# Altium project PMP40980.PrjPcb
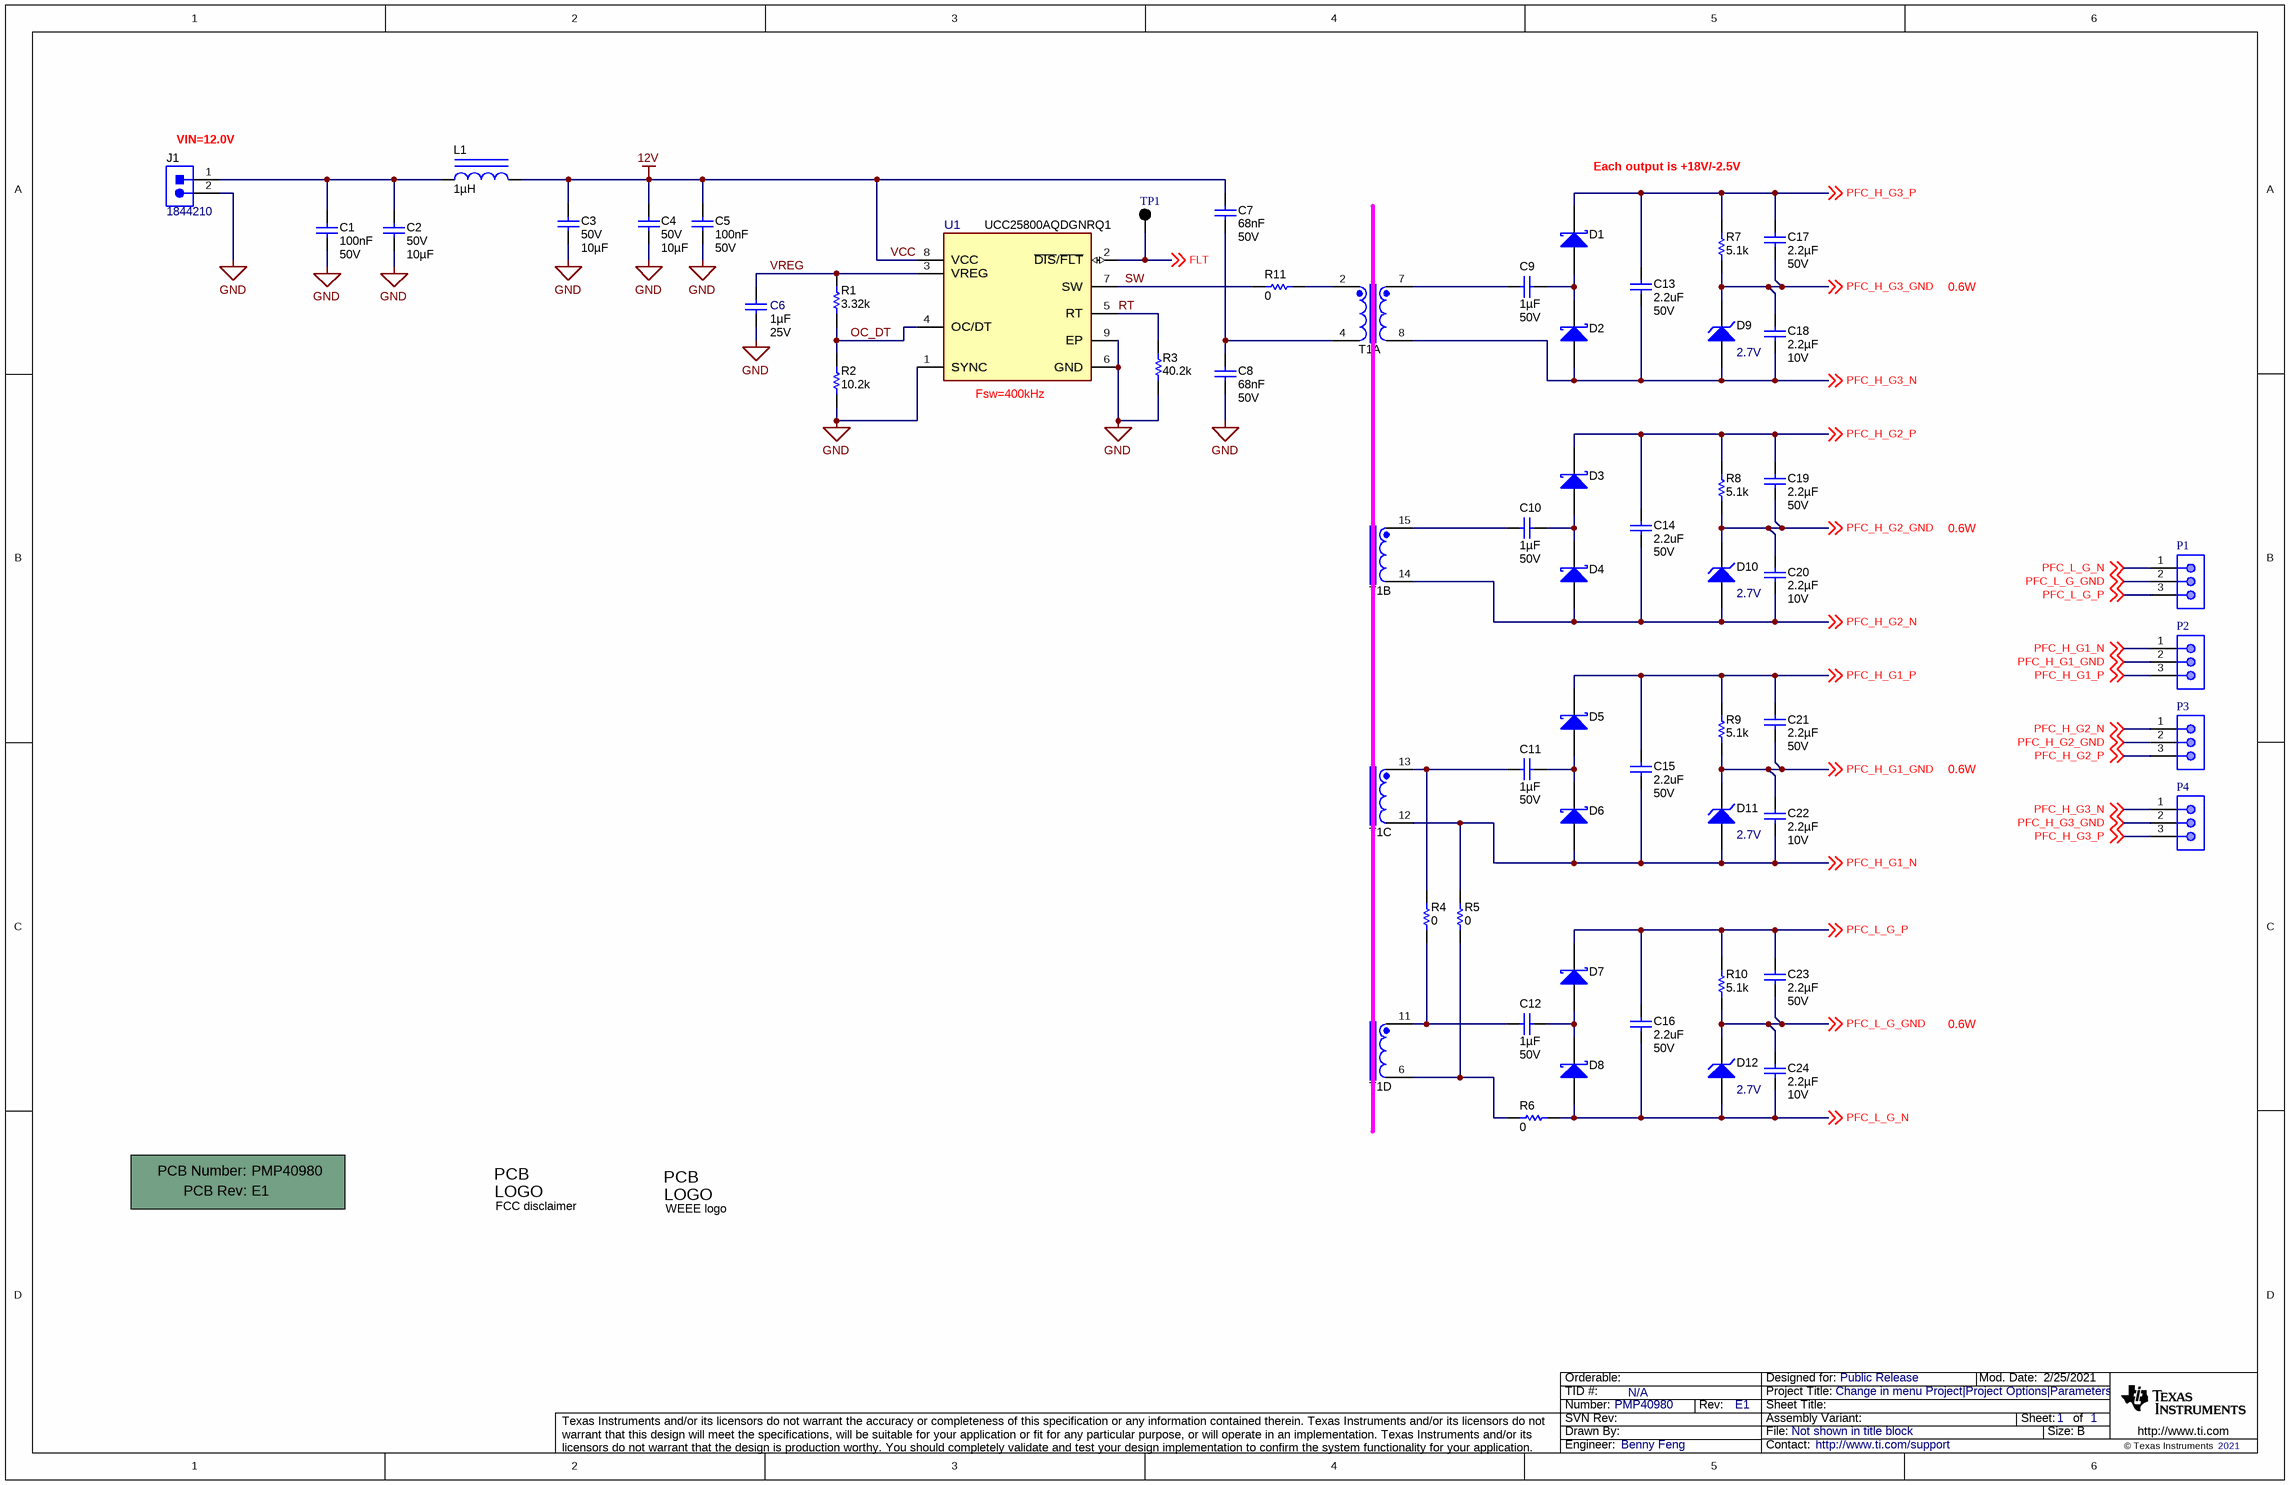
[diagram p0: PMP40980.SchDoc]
CopyrightYear: 2021; PCB_Layout: Benny Feng; PCB_Rev: E1; PRJ_Customer: Public Release; PRJ_Engineer: Benny Feng; PRJ_Number: PMP40980; PRJ_Title: Change in menu Project|Project Options|Parameters; SCH_Rev: E1; TechSupport: http://www.ti.com/support; TID: N/A
1 sheet, 59 parts. Net scope: global (net labels, ports and power ports of the same name join across sheets).
Board file: PMP40980.PcbDoc

## Sheet PMP40980.SchDoc
size 431 x 279 mm; Date: Not shown in title block; ApprovedBy: Not shown in title block; CheckedBy: Not shown in title block; Author: Not shown in title block; CompanyName: Not shown in title block; Engineer: Not shown in title block; Organization: Not shown in title block; Address1: Not shown in title block; Address2: Not shown in title block; Address3: Not shown in title block; Address4: Not shown in title block; DocumentNumber: 1; Revision: Use project parameter SCH_Rev; SheetNumber: 1; SheetTotal: 1; PageSetup: Record=PageOptions¦CenterHorizontal=True¦CenterVertical=True¦PrintScale=1.00¦XCorrection=1.00¦YCorrection=1.00¦PrintKind=0¦BorderSize=5000000¦LeftOffset=0¦BottomOffset=0¦Orientation=2¦PaperLength=1000¦PaperWidth=1000¦Scale=100¦PaperSource=15¦PrintQuality=600¦MediaType=1¦DitherType=10¦PaperKind=Letter¦PrintScaleMode=1

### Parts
!PCB1  Printed Circuit Board  (value not drawn)  (mechanical)
C1  Cap_F: 100nF  VDC_V: 50V  [0603L]  (hidden comment: CGA3E2X7R1H104K080AA)
C2  VDC_V: 50V  ValueDisplayed: 10µF  [1206_190L]  (hidden comment: CGA5L1X7R1H106K160AC)
C3  VDC_V: 50V  ValueDisplayed: 10µF  [1206_190L]  (hidden comment: CGA5L1X7R1H106K160AC)
C4  VDC_V: 50V  ValueDisplayed: 10µF  [1206_190L]  (hidden comment: CGA5L1X7R1H106K160AC)
C5  Cap_F: 100nF  VDC_V: 50V  [0603L]  (hidden comment: CGA3E2X7R1H104K080AA)
C6  Cap_F: 1µF  VDC_V: 25V  [0603L]  (hidden comment: CGA3E1X7R1E105K080AC)
C7  Cap_F: 68nF  VDC_V: 50V  [0805L]  (hidden comment: GCD21BR71H683KA01L)
C8  Cap_F: 68nF  VDC_V: 50V  [0805L]  (hidden comment: GCD21BR71H683KA01L)
C9  Cap_F: 1µF  VDC_V: 50V  [0805_HV1]  (hidden comment: CGA4J3X7R1H105K125AB)
C10  Cap_F: 1µF  VDC_V: 50V  [0805_HV1]  (hidden comment: CGA4J3X7R1H105K125AB)
C11  Cap_F: 1µF  VDC_V: 50V  [0805_HV1]  (hidden comment: CGA4J3X7R1H105K125AB)
C12  Cap_F: 1µF  VDC_V: 50V  [0805_HV1]  (hidden comment: CGA4J3X7R1H105K125AB)
C13  ValueDisplayed: 2.2uF  VDC_V: 50V  [1206_180L]  (hidden comment: GCM31CR71H225KA55L)
C14  ValueDisplayed: 2.2uF  VDC_V: 50V  [1206_180L]  (hidden comment: GCM31CR71H225KA55L)
C15  ValueDisplayed: 2.2uF  VDC_V: 50V  [1206_180L]  (hidden comment: GCM31CR71H225KA55L)
C16  ValueDisplayed: 2.2uF  VDC_V: 50V  [1206_180L]  (hidden comment: GCM31CR71H225KA55L)
C17  Cap_F: 2.2µF  VDC_V: 50V  [0805_HV1]  (hidden comment: CGA4J3X7R1H225K125AE)
C18  Cap_F: 2.2µF  VDC_V: 10V  [0805_HV1]  (hidden comment: GCM21BR71A225KA37L)
C19  Cap_F: 2.2µF  VDC_V: 50V  [0805_HV1]  (hidden comment: CGA4J3X7R1H225K125AE)
C20  Cap_F: 2.2µF  VDC_V: 10V  [0805_HV1]  (hidden comment: GCM21BR71A225KA37L)
C21  Cap_F: 2.2µF  VDC_V: 50V  [0805_HV1]  (hidden comment: CGA4J3X7R1H225K125AE)
C22  Cap_F: 2.2µF  VDC_V: 10V  [0805_HV1]  (hidden comment: GCM21BR71A225KA37L)
C23  Cap_F: 2.2µF  VDC_V: 50V  [0805_HV1]  (hidden comment: CGA4J3X7R1H225K125AE)
C24  Cap_F: 2.2µF  VDC_V: 10V  [0805_HV1]  (hidden comment: GCM21BR71A225KA37L)
D1  BAT165E6327HTSA1  [SOD-323]  (value not drawn)
D2  BAT165E6327HTSA1  [SOD-323]  (value not drawn)
D3  BAT165E6327HTSA1  [SOD-323]  (value not drawn)
D4  BAT165E6327HTSA1  [SOD-323]  (value not drawn)
D5  BAT165E6327HTSA1  [SOD-323]  (value not drawn)
D6  BAT165E6327HTSA1  [SOD-323]  (value not drawn)
D7  BAT165E6327HTSA1  [SOD-323]  (value not drawn)
D8  BAT165E6327HTSA1  [SOD-323]  (value not drawn)
D9  value 2.7V  [SOD-323]  (hidden comment: MMSZ5223BS-7-F)
D10  value 2.7V  [SOD-323]  (hidden comment: MMSZ5223BS-7-F)
D11  value 2.7V  [SOD-323]  (hidden comment: MMSZ5223BS-7-F)
D12  value 2.7V  [SOD-323]  (hidden comment: MMSZ5223BS-7-F)
J1  1844210  [Phoenix_1844210]
L1  ValueDisplayed: 1µH  [TFM322512]  (hidden comment: TFM322512ALMA1R0MTAA)
Logo1  FCC disclaimer  [FCC_disclaimer]  (no BOM)
Logo2  WEEE logo  [WEEE_Minimum]  (no BOM)
P1  61900311021  [61900311021]  (value not drawn)
P2  61900311021  [61900311021]  (value not drawn)
P3  61900311021  [61900311021]  (value not drawn)
P4  61900311021  [61900311021]  (value not drawn)
R1  ValueDisplayed: 3.32k  [0603L]  (hidden comment: CRCW06033K32FKEA)
R2  ValueDisplayed: 10.2k  [0603L]  (hidden comment: CRCW060310K2FKEA)
R3  ValueDisplayed: 40.2k  [0603L]  (hidden comment: ERJ-3EKF4022V)
R4  ValueDisplayed: 0  [0603_HV]  (hidden comment: CRCW06030000Z0EA)
R5  ValueDisplayed: 0  [0603_HV]  (hidden comment: CRCW06030000Z0EA)
R6  ValueDisplayed: 0  [0603_HV]  (hidden comment: CRCW06030000Z0EA)
R7  ValueDisplayed: 5.1k  [0805_HV1]  (hidden comment: ERJ-6GEYJ512V)
R8  ValueDisplayed: 5.1k  [0805_HV1]  (hidden comment: ERJ-6GEYJ512V)
R9  ValueDisplayed: 5.1k  [0805_HV1]  (hidden comment: ERJ-6GEYJ512V)
R10  ValueDisplayed: 5.1k  [0805_HV1]  (hidden comment: ERJ-6GEYJ512V)
R11  ValueDisplayed: 0  [0603_HV]  (hidden comment: CRCW06030000Z0EA)
T1  750345026  [Wurth_EPW15_13]  (value not drawn)  (parts A,B,C,D of 4)
TP1  5001  [Keystone5001]  (value not drawn)
U1  UCC25800AQDGNRQ1  [DGN0008G-MFG]

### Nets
GND: C1.2 C2.2 C3.2 C4.2 C5.2 C6.2 C8.2 J1.2 R2.1 R3.1 U1.1(SYNC) U1.6(GND) U1.9(EP)
VCC: C3.1 C4.1 C5.1 C7.1 L1.2 U1.8(VCC)  [also labelled 12V]
FLT: TP1.1 U1.2(~{DIS}/~{FLT}) ; off-sheet FLT
OC_DT: R1.1 R2.2 U1.4(OC/DT)
PFC_H_G1_GND: C21.2 C22.1 D11.1(K) P2.2 R9.1 ; off-sheet PFC_H_G1_GND
PFC_H_G1_N: C15.2 C22.2 D6.2(A) D11.2(A) P2.1 R5.2 T1.12 ; off-sheet PFC_H_G1_N
PFC_H_G1_P: C15.1 C21.1 D5.1(K) P2.3 R9.2 ; off-sheet PFC_H_G1_P
PFC_H_G2_GND: C19.2 C20.1 D10.1(K) P3.2 R8.1 ; off-sheet PFC_H_G2_GND
PFC_H_G2_N: C14.2 C20.2 D4.2(A) D10.2(A) P3.1 T1.14 ; off-sheet PFC_H_G2_N
PFC_H_G2_P: C14.1 C19.1 D3.1(K) P3.3 R8.2 ; off-sheet PFC_H_G2_P
PFC_H_G3_GND: C17.2 C18.1 D9.1(K) P4.2 R7.1 ; off-sheet PFC_H_G3_GND
PFC_H_G3_N: C13.2 C18.2 D2.2(A) D9.2(A) P4.1 T1.8 ; off-sheet PFC_H_G3_N
PFC_H_G3_P: C13.1 C17.1 D1.1(K) P4.3 R7.2 ; off-sheet PFC_H_G3_P
PFC_L_G_GND: C23.2 C24.1 D12.1(K) P1.2 R10.1 ; off-sheet PFC_L_G_GND
PFC_L_G_N: C16.2 C24.2 D8.2(A) D12.2(A) P1.1 R6.1 ; off-sheet PFC_L_G_N
PFC_L_G_P: C16.1 C23.1 D7.1(K) P1.3 R10.2 ; off-sheet PFC_L_G_P
RT: R3.2 U1.5(RT)
SW: R11.1 U1.7(SW)
VREG: C6.1 R1.2 U1.3(VREG)
NetC1_1: C1.1 C2.1 J1.1 L1.1
NetC7_2: C7.2 C8.1 T1.4
NetC9_1: C9.1 T1.7
NetC9_2: C9.2 D1.2(A) D2.1(K)
NetC10_1: C10.1 T1.15
NetC10_2: C10.2 D3.2(A) D4.1(K)
NetC11_1: C11.1 R4.2 T1.13
NetC11_2: C11.2 D5.2(A) D6.1(K)
NetC12_1: C12.1 R4.1 T1.11
NetC12_2: C12.2 D7.2(A) D8.1(K)
NetR5_1: R5.1 R6.2 T1.6
NetR11_2: R11.2 T1.2

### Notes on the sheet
- (near J1) VIN=12.0V
- Each output is +18V/-2.5V
- 0.6W
- (near U1) Fsw=400kHz

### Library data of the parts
!PCB1 = CMP-0003618-2: Manufacturer: Any; PartNumber: PMP40980
C1 C5 = CMP-0007078-3: CAP, CERM, 0.1 uF, 50 V, +/- 10%, X7R, AEC-Q200 Grade 1, 0603; Manufacturer: TDK; TaMin_C: -55°C; ESR_ohm: 0.0296; Polarized: N; SizeAreaWB_mm2: 4.68; Value1: 0.0296 ohm; U/M: EA; Value: 0.1uF; TaMax_C: 125°C; SizeZ_mm: 1; SizeX_mm: 1.6; SizeY_mm: 0.8; Cap_Case: 0603; SizeArea_mm2: 1.28; AEC Qualified: Y; IRMS_A: 971.99mA; AEC Category: Q200
C2-C4 = CMP-0085950-1: CAP, CERM, 10 µF, 50 V,+/- 10%, X7R, AEC-Q200 Grade 1, 1206; Manufacturer: TDK; TaMin_C: -55°C; Polarized: N; SizeAreaWB_mm2: 10.92; U/M: EA; Value: 10uF; TaMax_C: 125°C; SizeZ_mm: 1.9; SizeX_mm: 3.2; SizeY_mm: 1.6; Cap_Case: 1206; SizeArea_mm2: 5.12; AEC Qualified: Y; AEC Grade: 1; AEC Category: Q200
C6 = CMP-0076705-3: CAP, CERM, 1 µF, 25 V,+/- 10%, X7R, AEC-Q200 Grade 1, 0603; Manufacturer: TDK; SizeAreaWB_mm2: 4.68; SizeArea_mm2: 1.28; AEC Qualified: Y; AEC Category: Q200; Value: 1uF; TaMax_C: 125°C; SizeZ_mm: 1.0; AEC Grade: 1; Polarized: N; TaMin_C: -55°C; SizeY_mm: 0.8; U/M: EA; SizeX_mm: 1.6; Cap_Case: 1.6x0.8x0.8mm
C7 C8 = CMP-0008359-1: CAP, CERM, 0.068 uF, 50 V, +/- 10%, X7R, 0805; Manufacturer: MuRata; TaMin_C: -55°C; Polarized: N; SizeAreaWB_mm2: 6.75; U/M: EA; TaMax_C: 125°C; SizeZ_mm: 1.45; SizeX_mm: 2; SizeY_mm: 1.25; Cap_Case: 0805; SizeArea_mm2: 2.5; AEC Category: Q200; Value1: Unknown
C9-C12 = CMP-0007976-2: CAP, CERM, 1 uF, 50 V, +/- 10%, X7R, AEC-Q200 Grade 1, 0805; Manufacturer: TDK; TaMin_C: -55°C; ESR_ohm: 8.782m; Polarized: N; SizeAreaWB_mm2: 6.75; Value1: 0.008782 ohm; U/M: EA; Value: 1uF; TaMax_C: 125°C; SizeZ_mm: 1.45; SizeX_mm: 2; SizeY_mm: 1.25; Cap_Case: 0805; SizeArea_mm2: 2.5; AEC Qualified: Y; IRMS_A: 2.20488A; AEC Grade: 1; AEC Category: Q200
C13-C16 = CMP-0008814-1: CAP, CERM, 2.2 uF, 50 V, +/- 10%, X7R, AEC-Q200 Grade 1, 1206; Manufacturer: MuRata; SizeZ_mm: 1.8; Value: 2.2uF; Cap_Case: 1206; Cap_F: 2.2µF; AEC Grade: 1; Value1: Unknown; TaMin_C: -55°C; U/M: EA; SizeArea_mm2: 5.12; TaMax_C: 125°C; AEC Qualified: Y; AEC Category: Q200; SizeX_mm: 3.2; SizeY_mm: 1.6; Polarized: N; SizeAreaWB_mm2: 10.92
C17 C19 C21 C23 = CMP-0860897-1: CAP, CERM, 2.2 µF, 50 V,+/- 10%, X7R, AEC-Q200 Grade 1, 0805; Manufacturer: TDK; TaMin_C: -55°C; Polarized: N; SizeAreaWB_mm2: 6.75; U/M: EA; Value: 2.2uF; TaMax_C: 125°C; SizeZ_mm: 1.45; SizeX_mm: 2; SizeY_mm: 1.25; Cap_Case: 0805; SizeArea_mm2: 2.5; AEC Qualified: Y; AEC Grade: 1; AEC Category: Q200
C18 C20 C22 C24 = CMP-0008317-1: CAP, CERM, 2.2 uF, 10 V, +/- 10%, X7R, 0805; Manufacturer: MuRata; TaMin_C: -55°C; Polarized: N; SizeAreaWB_mm2: 6.75; Value1: 0.006 ohm; U/M: EA; Value: 2.2uF; TaMax_C: 125°C; SizeZ_mm: 1.45; SizeX_mm: 2; SizeY_mm: 1.25; Cap_Case: 0805; SizeArea_mm2: 2.5; AEC Qualified: Y; AEC Category: Q200; ESR_ohm: 6m
D1-D8 = CMP-0028882-1: Diode, Schottky, 40 V, 0.75 A, AEC-Q101, SOD-323; Manufacturer: Infineon Technologies; SizeAreaWB_mm2: 8.695; Vr_V: 40V; SizeArea_mm2: 3.645; AEC Qualified: Y; TJmax_C: 150°C; AEC Category: Q101; Value: 40V; SizeZ_mm: 1; Io_A: 750mA; Vf_V: 740mV; SizeY_mm: 1.35; Value2: 0.74V; Value1: 0.75A; SizeX_mm: 2.7; Green_Lifecycle: Not Set; Green_REACh: Incomplete; U/M: EA
D9-D12 = CMP-0005847-3: Diode, Zener, 2.7 V, 200 mW, SOD-323; Manufacturer: Diodes Inc.; SizeZ_mm: 1; RJA_CperW: 350; SizeAreaWB_mm2: 8.695; SizeX_mm: 2.7; SizeArea_mm2: 3.645; AEC Category: Q101; Power_W: 200mW; SizeY_mm: 1.35; Value1: 0.2W
J1 = CMP-0055556-1: Header(shrouded), 3.5mm, 2x1, Tin, TH; Manufacturer: Phoenix Contact; Cert_VDE: Y; CNHeader: FALSE; Current_A: 8A; Gender: Male; Voltage_V: 160V; Row_Count: 1; Pitch_mm: 3.5
L1 = CMP-0085828-1: Inductor, Thin Film, 1 µH, 4 A, 0.037 ohm, AEC-Q200 Grade 0, SMD; Manufacturer: TDK; Irms: 4A @ 40C rise; AEC Grade: 0; SizeArea_mm2: 8; AEC Qualified: Y; SizeX_mm: 3.2; SizeAreaWB_mm2: 14.7; Value2: 4A; AEC Category: Q200; SizeZ_mm: 1.2; DCR_ohm: 0.037; SizeY_mm: 2.5; Isat: 4.6A @ 30% inductance drop; Value: 1uH
Logo1 = CMP-0074847-1: FCC_disclaimer; Library Reference: Logo
Logo2 = CMP-0074769-1
P1-P4 = 61900311021: WR-WTB THT Male Left Angled Bottom Locking Header, pitch 2.54mm, 3p; Pin Number: 3; Contact Resistance: 20mOhm; Rated Current: 3A; Withstanding Voltage: 1000VAC; Working Voltage: 250VAC
R1 = CMP-0022375-4: RES, 3.32 k, 1%, 0.1 W, AEC-Q200 Grade 0, 0603; Manufacturer: Vishay-Dale; Power_W: 100mW; TempCo: 100 ppm/C; Value_Code: 3k32; Value: 3.32k; EIA_Code: E96; SizeX_mm: 1.6; SizeY_mm: 0.8; Value2: 0.1W; SizeArea_mm2: 1.28; AEC Qualified: Y; VDC_V: 75V; AEC Category: Q200; SizeZ_mm: 1; AEC Grade: 0
R2 = CMP-0021999-4: RES, 10.2 k, 1%, 0.1 W, AEC-Q200 Grade 0, 0603; Manufacturer: Vishay-Dale; Power_W: 100mW; TempCo: 100 ppm/C; Value_Code: 10k2; Value: 10.2k; EIA_Code: E96; SizeX_mm: 1.6; SizeY_mm: 0.8; SizeZ_mm: 1; Value2: 0.1W; SizeArea_mm2: 1.28; AEC Qualified: Y; VDC_V: 75V; AEC Category: Q200; AEC Grade: 0
R3 = CMP-0022700-1: RES, 40.2 k, 1%, 0.1 W, AEC-Q200 Grade 0, 0603; Manufacturer: Panasonic; Power_W: 100mW; TempCo: 100 ppm/C; Value_Code: 40k2; U/M: EA; Value: 40.2k; EIA_Code: E96; SizeX_mm: 1.6; SizeY_mm: 0.8; SizeZ_mm: 1; Value2: 0.1W; SizeArea_mm2: 1.28; AEC Qualified: Y; VDC_V: 75V; AEC Grade: 0; AEC Category: Q200
R4-R6 R11 = CMP-0025697-4: RES, 0, 5%, 0.1 W, AEC-Q200 Grade 0, 0603; Manufacturer: Vishay-Dale; Power_W: 100mW; TempCo: 200 ppm/C; Value_Code: 0000; Value: 0; EIA_Code: E24; SizeX_mm: 1.6; SizeY_mm: 0.8; SizeZ_mm: 1; Value2: 0.1W; SizeArea_mm2: 1.28; AEC Qualified: Y; VDC_V: 75V; AEC Category: Q200
R7-R10 = CMP-0020740-3: RES, 5.1 k, 5%, 0.125 W, AEC-Q200 Grade 0, 0805; Manufacturer: Panasonic; Power_W: 125mW; TempCo: 200 ppm/C; Value_Code: 5k10; Value: 5.1k; EIA_Code: E24; SizeX_mm: 2; SizeY_mm: 1.25; SizeZ_mm: 1.45; Value2: 0.125W; SizeArea_mm2: 2.5; AEC Qualified: Y; VDC_V: 150V; AEC Category: Q200; AEC Grade: 0; SizeAreaWB_mm2: 6.75
T1 = XFMR3: Manufacturer: Wurth; CompType: Transformer
TP1 = CMP-0055138-1: Test Point, Miniature, Black, TH; Manufacturer: Keystone; CNHeader: FALSE; Green_Lifecycle: Active; Green_REACh: Passed; ContactFinish: Silver; CT: TRUE
U1 = CMP-0088494-2: Open Loop LLC Transformer Driver for Isolated Bias Supplies; Manufacturer: Texas Instruments; Min Supply Voltage: 12V; SizeZ_mm: 1.1mm; Number Of Outputs: 1; Standoff Height: 0.05mm; AEC Category: Q200; Max Duty Cycle: 50%; TaMin_C: -40°C; TJmax_C: +150°C; AEC Qualified: No; Switching Frequency: 100-2000kHz; CompType: IC; Max Supply Voltage: 36V; TaMax_C: +125°C; Output Type: Other; Nominal Supply Current: 500uA

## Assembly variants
001: not fitted R4 R5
